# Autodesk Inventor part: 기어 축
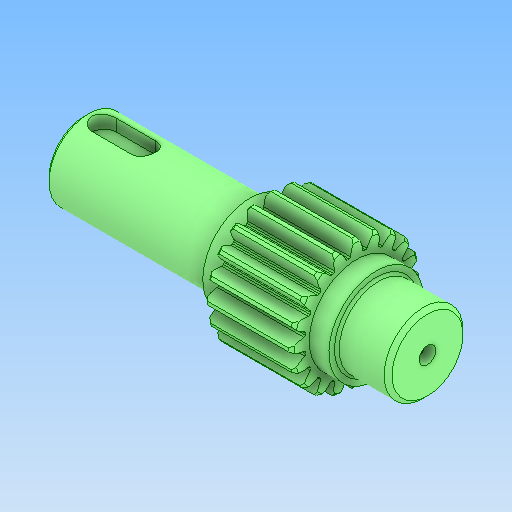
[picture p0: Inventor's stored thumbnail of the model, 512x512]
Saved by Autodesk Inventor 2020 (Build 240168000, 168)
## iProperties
Created: 2025-11
Part Number: 기어 축
Material: 강철, 합금
Document SubType Name: Modeling
Designer: PC2-06
Density: 7.73 g/cm^3
Appearance: 기본값
Author: jhkim
Sending System: Autodesk Inventor 2026
Preprocessor: ST-DEVELOPER v20.1
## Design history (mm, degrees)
feature "솔리드1"
node "솔리드2"
